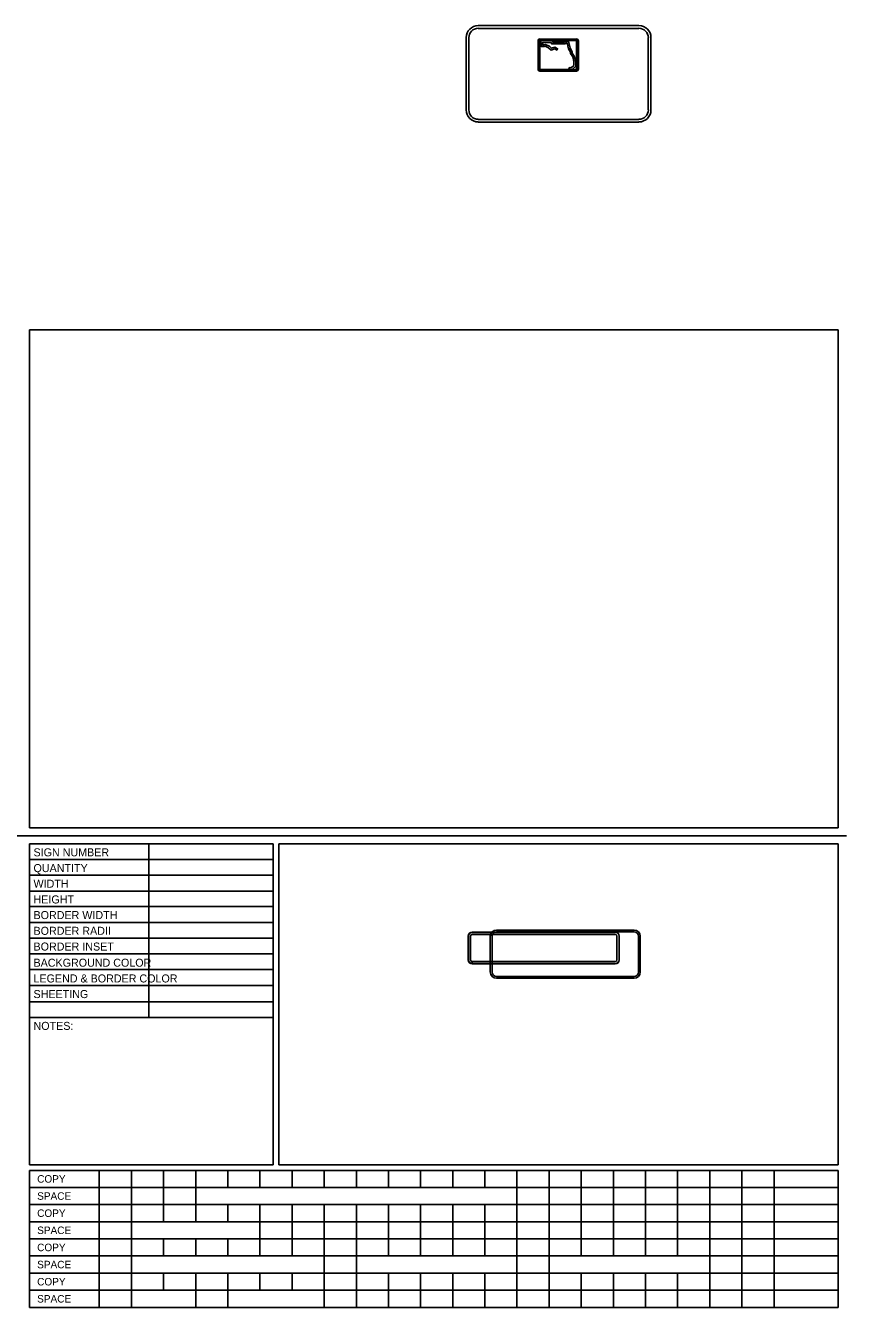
# Model space of a CAD drawing. Extents: x 10268197 to 10268511, y 2141503 to 2142677.
# Drawn here: x 10268395.1 to 10268471.7, y 2142384.2 to 2142504 of the extents above; entities that cross this region are included whole.
import ezdxf

# ---------------------------------------------------------------- set-up
doc = ezdxf.new("R2010")
doc.units = 0
for name, color, linetype in [('GSColorFill', 7, 'Continuous'), ('GSOutline', 7, 'Continuous'), ('SheetBorder_dp', 7, 'Continuous'), ('SumBoxLines_dp', 7, 'Continuous'), ('SumBoxLinesMin_dp', 7, 'Continuous'), ('TextMisc', 7, 'Continuous')]:
    doc.layers.add(name, color=color, linetype=linetype)

msp = doc.modelspace()

# ---------------------------------------------------------------- linework, layer by layer
at = {"layer": 'GSColorFill'}
for p, q in [((10268450.16, 2142419.28), (10268436.8, 2142419.28)), ((10268450.16, 2142419.28), (10268436.8, 2142419.28)), ((10268450.16, 2142419.28), (10268436.8, 2142419.28)), ((10268436.8, 2142419.26), (10268450.16, 2142419.26)), ((10268436.43, 2142418.91), (10268436.43, 2142416.69)), ((10268436.43, 2142418.91), (10268436.43, 2142416.69)), ((10268436.43, 2142418.91), (10268436.43, 2142416.69)), ((10268436.45, 2142416.69), (10268436.45, 2142418.91)), ((10268436.64, 2142416.69), (10268436.64, 2142418.91)), ((10268436.8, 2142419.07), (10268450.16, 2142419.07)), ((10268450.31, 2142418.91), (10268450.31, 2142416.69)), ((10268450.51, 2142418.91), (10268450.51, 2142416.69)), ((10268450.53, 2142416.69), (10268450.53, 2142418.91)), ((10268450.53, 2142416.69), (10268450.53, 2142418.91)), ((10268450.53, 2142416.69), (10268450.53, 2142418.91)), ((10268436.8, 2142416.32), (10268436.8, 2142416.53)), ((10268450.16, 2142416.53), (10268436.8, 2142416.53)), ((10268436.8, 2142416.53), (10268436.8, 2142416.32)), ((10268436.8, 2142416.32), (10268436.8, 2142416.34)), ((10268450.16, 2142416.34), (10268436.8, 2142416.34)), ((10268436.8, 2142416.34), (10268436.8, 2142416.32)), ((10268436.8, 2142416.32), (10268450.16, 2142416.32)), ((10268436.8, 2142416.32), (10268450.16, 2142416.32)), ((10268436.8, 2142416.32), (10268450.16, 2142416.32))]:
    msp.add_line(p, q, dxfattribs=at)
for centre, radius, start, end in [((10268436.8, 2142418.91), 0.371, 90, 180), ((10268436.8, 2142418.91), 0.371, 90, 180), ((10268436.8, 2142418.91), 0.371, 90, 180), ((10268436.8, 2142418.91), 0.349, 90, 180), ((10268450.16, 2142418.91), 0.371, 0, 90), ((10268450.16, 2142418.91), 0.371, 0, 90), ((10268450.16, 2142418.91), 0.371, 0, 90), ((10268450.16, 2142418.91), 0.349, 0, 90), ((10268436.8, 2142418.91), 0.155, 90, 180), ((10268450.16, 2142418.91), 0.155, 0, 90), ((10268436.8, 2142416.69), 0.371, 180, 270), ((10268436.8, 2142416.69), 0.371, 180, 270), ((10268436.8, 2142416.69), 0.371, 180, 270), ((10268436.8, 2142416.69), 0.349, 180, 270), ((10268436.8, 2142416.69), 0.155, 180, 270), ((10268450.16, 2142416.69), 0.371, 270, 0), ((10268450.16, 2142416.69), 0.371, 270, 0), ((10268450.16, 2142416.69), 0.155, 270, 0), ((10268450.16, 2142416.69), 0.371, 270, 0), ((10268450.16, 2142416.69), 0.349, 270, 0)]:
    msp.add_arc(centre, radius, start, end, dxfattribs=at)
at = {"layer": 'GSOutline'}
for p, q in [((10268452.37, 2142503.95), (10268437.36, 2142503.95)), ((10268452.37, 2142503.7), (10268437.36, 2142503.7)), ((10268436.24, 2142502.83), (10268436.24, 2142496.08)), ((10268436.49, 2142502.83), (10268436.49, 2142496.08)), ((10268442.96, 2142502.55), (10268442.96, 2142499.86)), ((10268442.99, 2142502.55), (10268442.99, 2142499.86)), ((10268446.55, 2142502.7), (10268443.11, 2142502.7)), ((10268446.55, 2142502.67), (10268443.11, 2142502.67)), ((10268446.67, 2142499.86), (10268446.67, 2142502.55)), ((10268446.71, 2142499.86), (10268446.71, 2142502.55)), ((10268453.24, 2142496.08), (10268453.24, 2142502.83)), ((10268453.49, 2142496.08), (10268453.49, 2142502.83)), ((10268443.11, 2142499.73), (10268446.55, 2142499.73)), ((10268443.11, 2142499.7), (10268446.55, 2142499.7)), ((10268437.36, 2142495.2), (10268452.37, 2142495.2)), ((10268437.36, 2142494.95), (10268452.37, 2142494.95)), ((10268450.16, 2142419.28), (10268436.8, 2142419.28)), ((10268451.91, 2142419.47), (10268439.07, 2142419.47)), ((10268451.91, 2142419.31), (10268439.07, 2142419.31)), ((10268436.43, 2142418.91), (10268436.43, 2142416.69)), ((10268436.64, 2142418.91), (10268436.64, 2142416.69)), ((10268450.16, 2142419.07), (10268436.8, 2142419.07)), ((10268438.49, 2142418.89), (10268438.49, 2142415.56)), ((10268438.66, 2142418.89), (10268438.66, 2142415.56)), ((10268450.31, 2142416.69), (10268450.31, 2142418.91)), ((10268450.53, 2142416.69), (10268450.53, 2142418.91)), ((10268452.33, 2142415.56), (10268452.33, 2142418.89)), ((10268452.49, 2142415.56), (10268452.49, 2142418.89)), ((10268436.8, 2142416.53), (10268450.16, 2142416.53)), ((10268436.8, 2142416.32), (10268450.16, 2142416.32)), ((10268439.07, 2142415.14), (10268451.91, 2142415.14)), ((10268439.07, 2142414.97), (10268451.91, 2142414.97))]:
    msp.add_line(p, q, dxfattribs=at)
for points in [[(10268443.11, 2142502.55), (10268443.11, 2142499.86), (10268446.55, 2142499.86), (10268446.55, 2142502.55)], [(10268445.9, 2142500.07), (10268445.99, 2142500.02), (10268446.08, 2142500.03), (10268446.3, 2142500.24), (10268446.3, 2142500.59), (10268446.19, 2142501.03), (10268445.98, 2142501.34), (10268445.99, 2142501.46), (10268445.78, 2142501.79), (10268445.67, 2142502.34), (10268445.56, 2142502.34), (10268445.5, 2142502.26), (10268444.2, 2142502.26), (10268444.16, 2142502.37), (10268443.37, 2142502.39), (10268443.39, 2142502.15), (10268443.5, 2142502.15), (10268443.6, 2142502.19), (10268444.01, 2142502.02), (10268444.21, 2142501.84), (10268444.52, 2142501.95), (10268444.77, 2142501.8), (10268444.69, 2142501.67), (10268444.51, 2142501.78), (10268444.17, 2142501.66), (10268443.93, 2142501.89), (10268443.6, 2142502.02), (10268443.52, 2142502), (10268443.25, 2142502), (10268443.21, 2142502.55), (10268444.27, 2142502.52), (10268444.31, 2142502.41), (10268445.42, 2142502.41), (10268445.47, 2142502.5), (10268445.79, 2142502.5), (10268445.93, 2142501.85), (10268446.14, 2142501.51), (10268446.14, 2142501.38), (10268446.33, 2142501.09), (10268446.46, 2142500.61), (10268446.46, 2142500.17), (10268446.15, 2142499.88), (10268445.95, 2142499.86), (10268445.83, 2142499.93)]]:
    msp.add_lwpolyline(points, close=True, dxfattribs=at)
for centre, radius, start, end in [((10268437.36, 2142502.83), 1.12, 90, 180), ((10268437.36, 2142502.83), 0.875, 90, 180), ((10268452.37, 2142502.83), 1.12, 0, 90), ((10268452.37, 2142502.83), 0.875, 0, 90), ((10268443.11, 2142502.55), 0.156, 90, 180), ((10268443.11, 2142502.55), 0.125, 90, 180), ((10268446.55, 2142502.55), 0.156, 0, 90), ((10268446.55, 2142502.55), 0.125, 0, 90), ((10268443.11, 2142499.86), 0.156, 180, 270), ((10268443.11, 2142499.86), 0.125, 180, 270), ((10268446.55, 2142499.86), 0.156, 270, 0), ((10268446.55, 2142499.86), 0.125, 270, 0), ((10268437.36, 2142496.08), 1.12, 180, 270), ((10268437.36, 2142496.08), 0.875, 180, 270), ((10268452.37, 2142496.08), 1.12, 270, 0), ((10268452.37, 2142496.08), 0.875, 270, 0), ((10268436.8, 2142418.91), 0.371, 90, 180), ((10268439.07, 2142418.89), 0.583, 90, 180), ((10268439.07, 2142418.89), 0.417, 90, 180), ((10268450.16, 2142418.91), 0.371, 0, 90), ((10268451.91, 2142418.89), 0.583, 0, 90), ((10268451.91, 2142418.89), 0.417, 0, 90), ((10268436.8, 2142418.91), 0.155, 90, 180), ((10268450.16, 2142418.91), 0.155, 0, 90), ((10268436.8, 2142416.69), 0.371, 180, 270), ((10268436.8, 2142416.69), 0.155, 180, 270), ((10268450.16, 2142416.69), 0.371, 270, 0), ((10268450.16, 2142416.69), 0.155, 270, 0), ((10268439.07, 2142415.56), 0.583, 180, 270), ((10268439.07, 2142415.56), 0.417, 180, 270), ((10268451.91, 2142415.56), 0.583, 270, 0), ((10268451.91, 2142415.56), 0.417, 270, 0)]:
    msp.add_arc(centre, radius, start, end, dxfattribs=at)
at = {"layer": 'SheetBorder_dp'}
msp.add_line((10268317.73, 2142428.28), (10268471.73, 2142428.28), dxfattribs=at)
at = {"layer": 'SumBoxLines_dp'}
for p, q in [((10268395.48, 2142475.53), (10268470.98, 2142475.53)), ((10268395.48, 2142475.53), (10268395.48, 2142429.03)), ((10268470.98, 2142475.53), (10268470.98, 2142429.03)), ((10268395.48, 2142429.03), (10268470.98, 2142429.03)), ((10268395.48, 2142427.53), (10268395.48, 2142397.53)), ((10268395.48, 2142427.53), (10268418.23, 2142427.53)), ((10268406.6, 2142427.53), (10268406.6, 2142411.31)), ((10268418.23, 2142427.53), (10268418.23, 2142397.53)), ((10268418.73, 2142427.53), (10268418.73, 2142397.53)), ((10268418.73, 2142427.53), (10268470.98, 2142427.53)), ((10268470.98, 2142427.53), (10268470.98, 2142397.53)), ((10268395.48, 2142426.07), (10268418.23, 2142426.07)), ((10268395.48, 2142424.59), (10268418.23, 2142424.59)), ((10268395.48, 2142423.12), (10268418.23, 2142423.12)), ((10268395.48, 2142421.66), (10268418.23, 2142421.66)), ((10268395.48, 2142420.19), (10268418.23, 2142420.19)), ((10268395.48, 2142418.73), (10268418.23, 2142418.73)), ((10268395.48, 2142417.26), (10268418.23, 2142417.26)), ((10268395.48, 2142415.79), (10268418.23, 2142415.79)), ((10268395.48, 2142414.31), (10268418.23, 2142414.31)), ((10268395.48, 2142412.78), (10268418.23, 2142412.78)), ((10268395.48, 2142411.31), (10268418.23, 2142411.31)), ((10268395.48, 2142397.53), (10268418.23, 2142397.53)), ((10268395.48, 2142397.03), (10268470.98, 2142397.03)), ((10268395.48, 2142397.03), (10268395.48, 2142384.23)), ((10268401.98, 2142397.03), (10268401.98, 2142384.23)), ((10268404.98, 2142397.03), (10268404.98, 2142384.23)), ((10268407.98, 2142397.03), (10268407.98, 2142393.83)), ((10268410.98, 2142397.03), (10268410.98, 2142393.83)), ((10268413.98, 2142397.03), (10268413.98, 2142395.43)), ((10268416.98, 2142397.03), (10268416.98, 2142395.43)), ((10268418.73, 2142397.53), (10268470.98, 2142397.53)), ((10268419.98, 2142397.03), (10268419.98, 2142395.43)), ((10268422.98, 2142397.03), (10268422.98, 2142395.43)), ((10268425.98, 2142397.03), (10268425.98, 2142395.43)), ((10268428.98, 2142397.03), (10268428.98, 2142395.43)), ((10268431.98, 2142397.03), (10268431.98, 2142395.43)), ((10268434.98, 2142397.03), (10268434.98, 2142395.43)), ((10268437.98, 2142397.03), (10268437.98, 2142395.43)), ((10268440.98, 2142397.03), (10268440.98, 2142393.83)), ((10268443.98, 2142397.03), (10268443.98, 2142393.83)), ((10268446.98, 2142397.03), (10268446.98, 2142395.43)), ((10268449.98, 2142397.03), (10268449.98, 2142395.43)), ((10268452.98, 2142397.03), (10268452.98, 2142395.43)), ((10268455.98, 2142397.03), (10268455.98, 2142395.43)), ((10268458.98, 2142397.03), (10268458.98, 2142395.43)), ((10268461.98, 2142397.03), (10268461.98, 2142395.43)), ((10268464.98, 2142397.03), (10268464.98, 2142395.43)), ((10268470.98, 2142397.03), (10268470.98, 2142384.23)), ((10268440.98, 2142395.43), (10268440.98, 2142387.43)), ((10268443.98, 2142395.43), (10268443.98, 2142389.03)), ((10268446.98, 2142395.43), (10268446.98, 2142389.03)), ((10268449.98, 2142395.43), (10268449.98, 2142389.03)), ((10268452.98, 2142395.43), (10268452.98, 2142389.03)), ((10268455.98, 2142395.43), (10268455.98, 2142389.03)), ((10268458.98, 2142395.43), (10268458.98, 2142389.03)), ((10268461.98, 2142395.43), (10268461.98, 2142389.03)), ((10268464.98, 2142395.43), (10268464.98, 2142384.23)), ((10268395.48, 2142393.83), (10268470.98, 2142393.83)), ((10268407.98, 2142393.83), (10268407.98, 2142392.23)), ((10268410.98, 2142393.83), (10268410.98, 2142392.23)), ((10268413.98, 2142393.83), (10268413.98, 2142392.23)), ((10268416.98, 2142393.83), (10268416.98, 2142390.63)), ((10268419.98, 2142393.83), (10268419.98, 2142390.63)), ((10268422.98, 2142393.83), (10268422.98, 2142390.63)), ((10268425.98, 2142393.83), (10268425.98, 2142390.63)), ((10268428.98, 2142393.83), (10268428.98, 2142390.63)), ((10268431.98, 2142393.83), (10268431.98, 2142389.03)), ((10268434.98, 2142393.83), (10268434.98, 2142389.03)), ((10268437.98, 2142393.83), (10268437.98, 2142389.03)), ((10268395.48, 2142390.63), (10268470.98, 2142390.63)), ((10268407.98, 2142390.63), (10268407.98, 2142389.03)), ((10268410.98, 2142390.63), (10268410.98, 2142389.03)), ((10268413.98, 2142390.63), (10268413.98, 2142389.03)), ((10268416.98, 2142390.63), (10268416.98, 2142389.03)), ((10268419.98, 2142390.63), (10268419.98, 2142389.03)), ((10268422.98, 2142390.63), (10268422.98, 2142387.43)), ((10268425.98, 2142390.63), (10268425.98, 2142387.43)), ((10268428.98, 2142390.63), (10268428.98, 2142389.03)), ((10268443.98, 2142389.03), (10268443.98, 2142384.23)), ((10268458.98, 2142389.03), (10268458.98, 2142384.23)), ((10268461.98, 2142389.03), (10268461.98, 2142384.23)), ((10268395.48, 2142387.43), (10268470.98, 2142387.43)), ((10268407.98, 2142387.43), (10268407.98, 2142385.83)), ((10268410.98, 2142387.43), (10268410.98, 2142384.23)), ((10268413.98, 2142387.43), (10268413.98, 2142384.23)), ((10268416.98, 2142387.43), (10268416.98, 2142385.83)), ((10268419.98, 2142387.43), (10268419.98, 2142385.83)), ((10268422.98, 2142387.43), (10268422.98, 2142384.23)), ((10268425.98, 2142387.43), (10268425.98, 2142384.23)), ((10268428.98, 2142387.43), (10268428.98, 2142384.23)), ((10268431.98, 2142387.43), (10268431.98, 2142384.23)), ((10268434.98, 2142387.43), (10268434.98, 2142384.23)), ((10268437.98, 2142387.43), (10268437.98, 2142384.23)), ((10268440.98, 2142387.43), (10268440.98, 2142384.23)), ((10268446.98, 2142387.43), (10268446.98, 2142384.23)), ((10268449.98, 2142387.43), (10268449.98, 2142384.23)), ((10268452.98, 2142387.43), (10268452.98, 2142384.23)), ((10268455.98, 2142387.43), (10268455.98, 2142384.23)), ((10268395.48, 2142384.23), (10268470.98, 2142384.23))]:
    msp.add_line(p, q, dxfattribs=at)
at = {"layer": 'SumBoxLinesMin_dp'}
for p, q in [((10268395.48, 2142395.43), (10268470.98, 2142395.43)), ((10268395.48, 2142392.23), (10268470.98, 2142392.23)), ((10268395.48, 2142389.03), (10268470.98, 2142389.03)), ((10268395.48, 2142385.83), (10268470.98, 2142385.83))]:
    msp.add_line(p, q, dxfattribs=at)

# ---------------------------------------------------------------- texts
at = {"layer": 'TextMisc'}
for s, height, p in [('SIGN NUMBER', 0.7476, (10268395.84, 2142426.36)), ('QUANTITY', 0.748, (10268395.84, 2142424.89)), ('WIDTH', 0.748, (10268395.84, 2142423.43)), ('HEIGHT', 0.748, (10268395.84, 2142421.96)), ('BORDER WIDTH', 0.7476, (10268395.84, 2142420.5)), ('BORDER RADII', 0.7476, (10268395.84, 2142419.03)), ('BORDER INSET', 0.7476, (10268395.84, 2142417.56)), ('BACKGROUND COLOR', 0.7476, (10268395.84, 2142416.05)), ('LEGEND & BORDER COLOR', 0.7476, (10268395.84, 2142414.58)), ('SHEETING', 0.748, (10268395.84, 2142413.12)), ('NOTES:', 0.748, (10268395.84, 2142410.15)), ('COPY', 0.7, (10268396.18, 2142395.88)), ('SPACE', 0.7, (10268396.18, 2142394.28)), ('COPY', 0.7, (10268396.18, 2142392.68)), ('SPACE', 0.7, (10268396.18, 2142391.08)), ('COPY', 0.7, (10268396.18, 2142389.48)), ('SPACE', 0.7, (10268396.18, 2142387.88)), ('COPY', 0.7, (10268396.18, 2142386.28)), ('SPACE', 0.7, (10268396.18, 2142384.68))]:
    msp.add_text(s, height=height, dxfattribs=at).set_placement(p)

doc.saveas('drawing.dxf')
